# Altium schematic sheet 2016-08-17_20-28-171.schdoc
size 425 x 220 mm; SheetNumber: 1; SheetTotal: 1
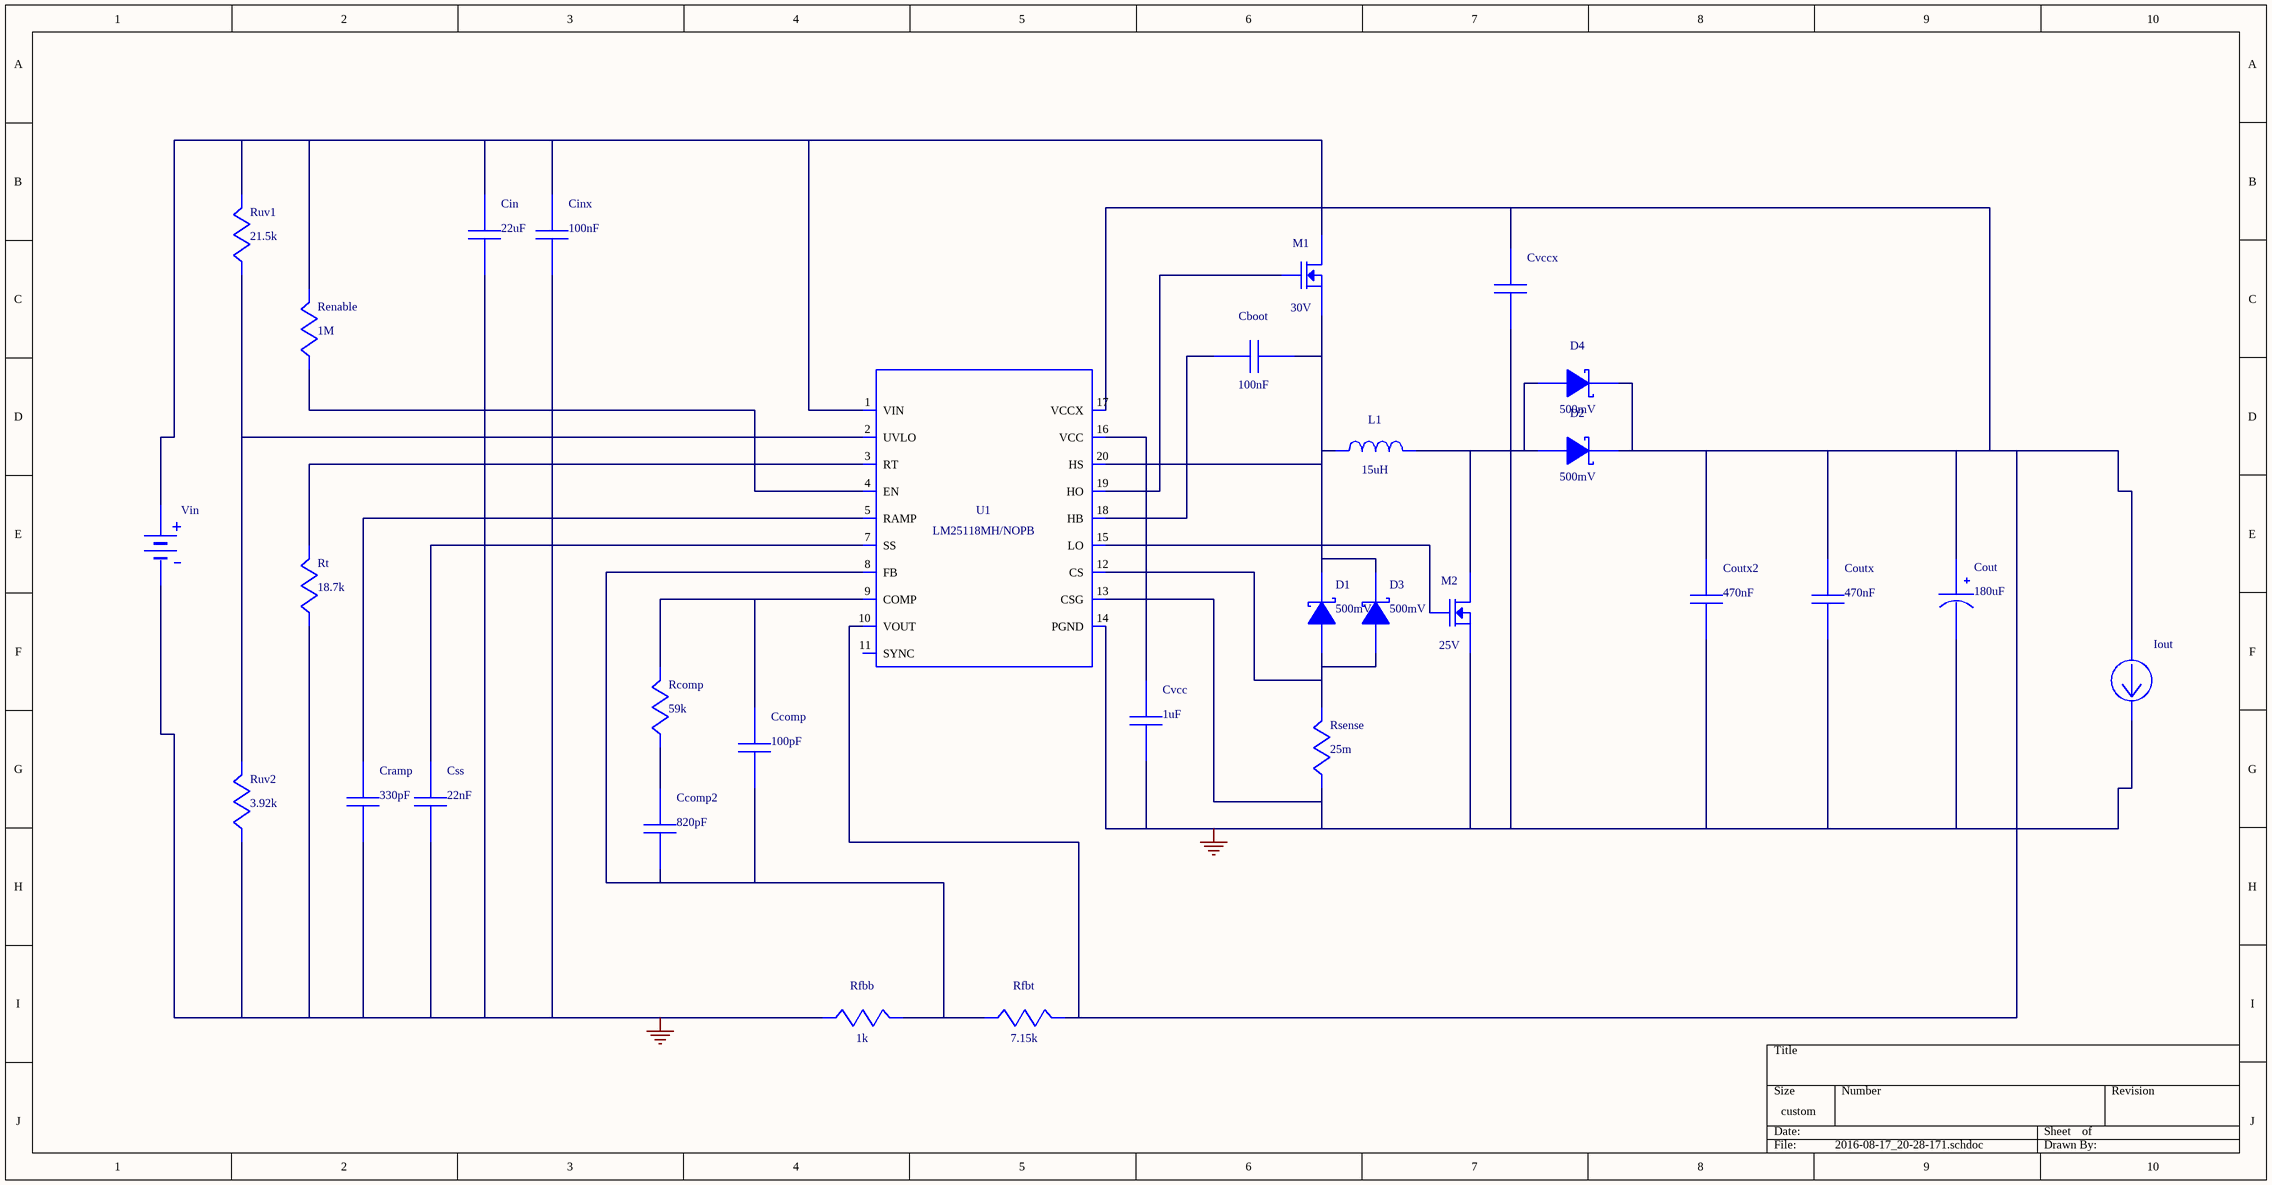
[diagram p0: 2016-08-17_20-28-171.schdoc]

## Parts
Cboot  value 100nF  (hidden comment: GRM21BR71E104KA01L)
Ccomp  value 100pF  (hidden comment: CC0805JRNPO9BN101)
Ccomp2  value 820pF  (hidden comment: CC0805KRX7R9BB821)
Cin  value 22uF  (hidden comment: GRM32ER61E226KE15L)
Cinx  value 100nF  (hidden comment: 08053C104KAT2A)
Cout  value 180uF  (hidden comment: APXA160ARA181MHC0G)
Coutx  value 470nF  (hidden comment: GRM188R71C474KA88D)
Coutx2  value 470nF  (hidden comment: GRM188R71C474KA88D)
Cramp  value 330pF  (hidden comment: CL21C331JBANFNC)
Css  value 22nF  (hidden comment: CC0805KRX7R9BB223)
Cvcc  value 1uF  (hidden comment: EMK212B7105KG-T)
Cvccx  GRM21BR71E104KA01L  (value not drawn)
D1  value 500mV  (hidden comment: B340A-13-F)
D2  value 500mV  (hidden comment: B340A-13-F)
D3  value 500mV  (hidden comment: B340A-13-F)
D4  value 500mV  (hidden comment: B340A-13-F)
Iout  WB_CURRENT_LOAD  (value not drawn)
L1  value 15uH  (hidden comment: SRR1210-150M)
M1  value 30V  (hidden comment: CSD17308Q3)
M2  value 25V  (hidden comment: CSD16323Q3)
Rcomp  value 59k  (hidden comment: CRCW040259K0FKED)
Renable  value 1M  (hidden comment: CRCW04021M00FKED)
Rfbb  value 1k  (hidden comment: CRCW04021K00FKED)
Rfbt  value 7.15k  (hidden comment: CRCW04027K15FKED)
Rsense  value 25m  (hidden comment: CSR1206FK25L0)
Rt  value 18.7k  (hidden comment: CRCW040218K7FKED)
Ruv1  value 21.5k  (hidden comment: CRCW040221K5FKED)
Ruv2  value 3.92k  (hidden comment: CRCW04023K92FKED)
U1  LM25118MH/NOPB
Vin  WB_BATTERY  (value not drawn)

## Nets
0: Cin.2 Cinx.2 Cout.2(-) Coutx.2 Coutx2.2 Cramp.2 Css.2 Cvcc.2 Cvccx.1 Iout.2(-) M2.1(Source) M2.2(Source) M2.3(Source) Rfbb.2 Rsense.2 Rt.2 Ruv2.2 U1.6(AGND) U1.13(CSG) U1.14(PGND) U1.21(EXP-PAD) Vin.2(-)
NetCboot_1: Cboot.1 D1.1(K) D3.1(K) L1.2 M1.1(Source) M1.2(Source) M1.3(Source) U1.20(HS)
NetCboot_2: Cboot.2 U1.18(HB)
NetCcomp2_1: Ccomp2.1 Rcomp.2
NetCcomp_1: Ccomp.1 Rcomp.1 U1.9(COMP)
NetCcomp_2: Ccomp.2 Ccomp2.2 Rfbb.1 Rfbt.2 U1.8(FB)
NetCin_1: Cin.1 Cinx.1 M1.5(Drain) M1.6(Drain) M1.7(Drain) M1.8(Drain) M1.9(Drain) Renable.1 Ruv1.1 U1.1(VIN) Vin.1(+)
NetCout_1: Cout.1(+) Coutx.1 Coutx2.1 Cvccx.2 D2.1(K) D4.1(K) Iout.1(+) Rfbt.1 U1.10(VOUT) U1.17(VCCX)
NetCramp_1: Cramp.1 U1.5(RAMP)
NetCss_1: Css.1 U1.7(SS)
NetCvcc_1: Cvcc.1 U1.16(VCC)
NetD1_2: D1.2(A) D3.2(A) Rsense.1 U1.12(CS)
NetD2_2: D2.2(A) D4.2(A) L1.1 M2.5(Drain) M2.6(Drain) M2.7(Drain) M2.8(Drain) M2.9(Drain)
NetM1_4: M1.4(Gate) U1.19(HO)
NetM2_4: M2.4(Gate) U1.15(LO)
NetRenable_2: Renable.2 U1.4(EN)
NetRt_1: Rt.1 U1.3(RT)
NetRuv1_2: Ruv1.2 Ruv2.1 U1.2(UVLO)

Not connected (* = marked no-connect by the designer): U1 11(SYNC)

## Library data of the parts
Cboot = GRM21BR71E104KA01L: GRM21BR71E104KA0; Manufacturer Name: MuRata
Ccomp = CC0805JRNPO9BN101: CC0805JRNPO9BN10; Manufacturer Name: Yageo America
Ccomp2 = CC0805KRX7R9BB821: CC0805KRX7R9BB82; Manufacturer Name: Yageo America
Cin = GRM32ER61E226KE15L: GRM32ER61E226KE1; Manufacturer Name: MuRata
Cinx = 08053C104KAT2A: Manufacturer Name: AVX
Cout = APXA160ARA181MHC0G: APXA160ARA181MHC; Manufacturer Name: Chemi-Con
Coutx Coutx2 = GRM188R71C474KA88D: GRM188R71C474KA8; Manufacturer Name: MuRata
Cramp = CL21C331JBANFNC: Manufacturer Name: Samsung Electro-Mechanics
Css = CC0805KRX7R9BB223: CC0805KRX7R9BB22; Manufacturer Name: Yageo America
Cvcc = EMK212B7105KG-T: Manufacturer Name: Taiyo Yuden
Cvccx = GRM21BR71E104KA01L: WB_PRIMITIVE_CAP; Manufacturer Name: WB_PRIMITIVE_CAPACITOR
D1-D4 = B340A-13-F: Manufacturer Name: Diodes Inc.
L1 = SRR1210-150M: Manufacturer Name: Bourns
M1 = CSD17308Q3: Manufacturer Name: Texas Instruments
M2 = CSD16323Q3: Manufacturer Name: Texas Instruments
Rcomp = CRCW040259K0FKED: Manufacturer Name: Vishay-Dale
Renable = CRCW04021M00FKED: Manufacturer Name: Vishay-Dale
Rfbb = CRCW04021K00FKED: Manufacturer Name: Vishay-Dale
Rfbt = CRCW04027K15FKED: Manufacturer Name: Vishay-Dale
Rsense = CSR1206FK25L0: Manufacturer Name: Stackpole Electronics Inc
Rt = CRCW040218K7FKED: Manufacturer Name: Vishay-Dale
Ruv1 = CRCW040221K5FKED: Manufacturer Name: Vishay-Dale
Ruv2 = CRCW04023K92FKED: Manufacturer Name: Vishay-Dale
U1 = LM25118MH/NOPB: Manufacturer Name: Texas Instruments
